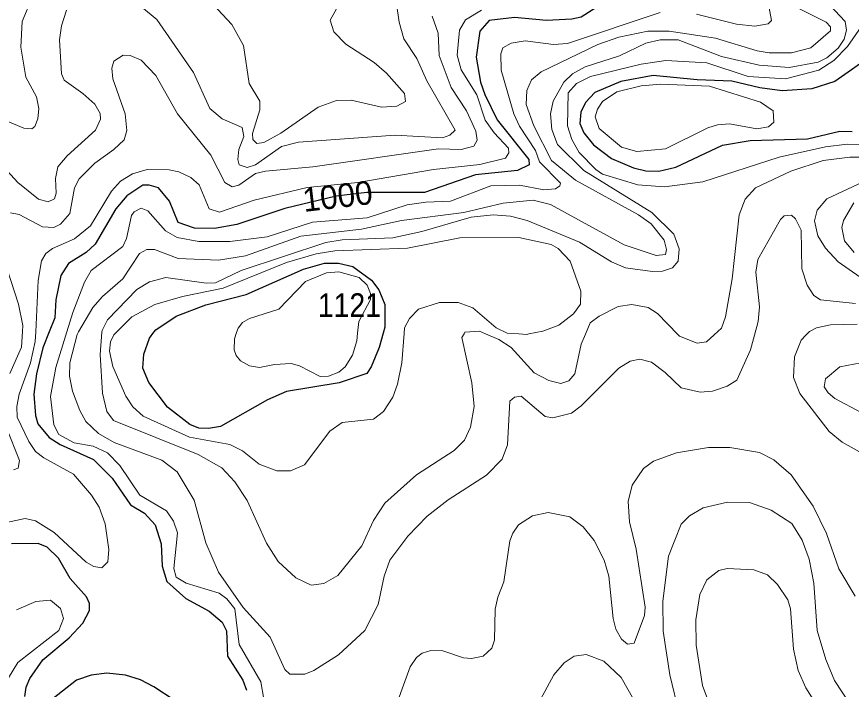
# Model space of a CAD drawing. Extents: x 473.9 to 500, y 7733.1 to 7760.8.
# Drawn here: x 479.07 to 481.9, y 7739.929 to 7742.209 of the extents above; entities that cross this region are included whole.
import ezdxf
from ezdxf.enums import TextEntityAlignment as Align

# ---------------------------------------------------------------- set-up
doc = ezdxf.new("R2010")
doc.units = 0
doc.header["$LTSCALE"] = 0.032
doc.layers.add('1', color=7, linetype='Continuous', lineweight=25)
doc.layers.add('2', color=7, linetype='Continuous', lineweight=13)
doc.layers.add('21', color=7, linetype='Continuous')
doc.layers.add('61', color=7, linetype='Continuous')

msp = doc.modelspace()

# ---------------------------------------------------------------- linework, layer by layer
at = {"layer": '1'}
for points in [[(481.0493, 7742.2496), (480.9842, 7742.2075), (480.9529, 7742.2003), (480.866, 7742.1958), (480.7586, 7742.2062), (480.6717, 7742.196), (480.6409, 7742.1598), (480.6279, 7742.0722), (480.6431, 7741.9876), (480.6572, 7741.9454), (480.699, 7741.8597), (480.8072, 7741.7253), (480.8075, 7741.707), (480.7685, 7741.6876), (480.6264, 7741.6727), (480.4528, 7741.6134), (480.2574, 7741.613), (480.1533, 7741.6001), (479.9797, 7741.5588), (479.8172, 7741.5043), (479.7406, 7741.4906), (479.6731, 7741.4918), (479.6173, 7741.511), (479.5883, 7741.5841), (479.5506, 7741.6288), (479.52, 7741.6381), (479.4977, 7741.6381), (479.4442, 7741.6014), (479.4062, 7741.5576), (479.336, 7741.4374), (479.3058, 7741.4094), (479.2456, 7741.3723), (479.2195, 7741.3317), (479.2031, 7741.2486), (479.1994, 7741.1878), (479.1808, 7741.1409), (479.159, 7741.0859), (479.1372, 7740.9983), (479.1289, 7740.9297), (479.1338, 7740.8567), (479.142, 7740.8288), (479.1807, 7740.7827), (479.2183, 7740.7591), (479.3309, 7740.7081), (479.3943, 7740.6447), (479.4558, 7740.5541), (479.5036, 7740.5257), (479.5396, 7740.4868), (479.56, 7740.4224), (479.5633, 7740.3459), (479.5796, 7740.2945), (479.6438, 7740.2366), (479.7234, 7740.1937), (479.7673, 7740.1566), (479.7811, 7740.1265)], [(481.9763, 7742.0816), (481.8439, 7741.9894), (481.7658, 7741.9639), (481.6658, 7741.9577), (481.5895, 7741.9679), (481.4954, 7741.9899), (481.3774, 7741.9945), (481.2284, 7742.0092), (481.1182, 7741.989), (481.0309, 7741.9516), (480.9991, 7741.9177), (480.9831, 7741.8853), (480.9791, 7741.8472), (480.9935, 7741.815), (481.0258, 7741.7751), (481.087, 7741.7281), (481.1611, 7741.6967), (481.2033, 7741.6867), (481.2473, 7741.6852), (481.3046, 7741.6987), (481.4633, 7741.7733), (481.5568, 7741.789), (481.7511, 7741.7953), (481.861, 7741.8209), (481.9032, 7741.8195)], [(479.0977, 7739.9039), (479.102, 7739.9364), (479.1144, 7739.9652), (479.1592, 7740.0285), (479.2484, 7740.1032), (479.2946, 7740.1527), (479.3171, 7740.1964), (479.3169, 7740.22), (479.3073, 7740.2419), (479.2516, 7740.3044), (479.2121, 7740.3732), (479.1734, 7740.411), (479.1428, 7740.4228), (479.0522, 7740.4219)], [(479.7811, 7740.1265), (479.7852, 7740.0411), (479.8373, 7739.9597), (479.8493, 7739.9256)], [(479.6727, 7739.8471), (479.5355, 7739.937), (479.4897, 7739.9609), (479.4393, 7739.9773), (479.3762, 7739.983), (479.323, 7739.9772), (479.2727, 7739.9599), (479.1628, 7739.8728)]]:
    msp.add_lwpolyline(points, dxfattribs=at)
msp.add_lwpolyline([(480.2995, 7741.0878), (480.2726, 7741.022), (480.2572, 7740.9999), (480.1642, 7740.9677), (479.9855, 7740.9387), (479.9212, 7740.9097), (479.7615, 7740.8202), (479.7204, 7740.813), (479.6879, 7740.8145), (479.6572, 7740.8265), (479.5811, 7740.885), (479.5182, 7740.9684), (479.4982, 7741.0173), (479.501, 7741.0648), (479.5202, 7741.1194), (479.5355, 7741.1393), (479.5417, 7741.1473), (479.6109, 7741.1943), (479.7117, 7741.2318), (479.8483, 7741.2673), (480.0424, 7741.353), (480.1134, 7741.3738), (480.1613, 7741.3731), (480.2099, 7741.3627), (480.273, 7741.3159), (480.2983, 7741.2827), (480.3179, 7741.233), (480.3187, 7741.1562), (480.3129, 7741.1357)], close=True, dxfattribs=at)
at = {"layer": '2'}
for points in [[(479.1239, 7742.2775), (479.0893, 7742.193), (479.0847, 7742.106), (479.1011, 7742.0039), (479.1373, 7741.9378), (479.1459, 7741.8977), (479.1425, 7741.8623), (479.1324, 7741.8372), (479.1215, 7741.8291), (479.0948, 7741.8312), (479.025, 7741.8608)], [(480.1645, 7742.2535), (480.1333, 7742.1967), (480.1461, 7742.1578), (480.1866, 7742.1159), (480.2819, 7742.0533), (480.3238, 7742.0171), (480.3849, 7741.9487), (480.3887, 7741.9214), (480.3586, 7741.9053), (480.3071, 7741.9022), (480.2042, 7741.9255), (480.1549, 7741.9251), (480.0927, 7741.9025), (479.9656, 7741.8142), (479.9083, 7741.7821), (479.8842, 7741.779), (479.8707, 7741.7925), (479.8695, 7741.8129), (479.8952, 7741.8934), (479.8943, 7741.9228), (479.8581, 7741.9823), (479.8396, 7742.111), (479.7999, 7742.1824), (479.7212, 7742.2684)], [(481.612, 7742.2889), (481.6292, 7742.1966), (481.618, 7742.1846), (481.5728, 7742.177), (481.5108, 7742.1837), (481.3749, 7742.2174)], [(481.1835, 7741.0475), (481.1502, 7741.041), (481.1114, 7741.0171), (480.9837, 7740.8895), (480.9509, 7740.8651), (480.8876, 7740.849), (480.8626, 7740.8538), (480.7804, 7740.9226), (480.7578, 7740.9193), (480.742, 7740.9053), (480.7348, 7740.758), (480.7159, 7740.7092), (480.6627, 7740.6545), (480.5335, 7740.571), (480.4621, 7740.5152), (480.3962, 7740.4485), (480.3354, 7740.3663), (480.316, 7740.3121), (480.2961, 7740.2161), (480.2501, 7740.1282), (480.161, 7740.0459), (480.0782, 7739.9923), (480.0477, 7739.9796), (479.9969, 7739.9796), (479.9795, 7739.9955), (479.9302, 7740.1057), (479.8385, 7740.2062), (479.7544, 7740.3261), (479.7117, 7740.4257), (479.6716, 7740.5699), (479.6146, 7740.6664), (479.562, 7740.7056), (479.4008, 7740.7654), (479.348, 7740.7964), (479.3052, 7740.8372), (479.2839, 7740.8744), (479.2601, 7740.9399), (479.2499, 7740.9901), (479.2504, 7741.0357), (479.275, 7741.1317), (479.2801, 7741.1405), (479.3284, 7741.2228), (479.3607, 7741.2599), (479.43, 7741.3206), (479.4872, 7741.4065), (479.5117, 7741.4203), (479.5374, 7741.4196), (479.6178, 7741.3893), (479.754, 7741.3838), (479.8457, 7741.398), (480.0332, 7741.4649), (480.2391, 7741.4888), (480.3753, 7741.5186), (480.5864, 7741.5451), (480.7198, 7741.5763), (480.8212, 7741.5871), (480.8801, 7741.5725), (481.13, 7741.4355), (481.2382, 7741.3999), (481.2695, 7741.4023), (481.2732, 7741.4195), (481.2658, 7741.4516), (481.2214, 7741.507), (481.1789, 7741.5371), (480.9654, 7741.6546), (480.8837, 7741.722), (480.8235, 7741.8393), (480.798, 7741.9112), (480.7996, 7741.9588), (480.8158, 7741.9951), (480.8484, 7742.0223), (481.0401, 7742.1151), (481.1117, 7742.1397), (481.2097, 7742.1594), (481.2821, 7742.1594), (481.4399, 7742.1365), (481.5807, 7742.0937), (481.621, 7742.087), (481.6976, 7742.087), (481.7629, 7742.1033), (481.8296, 7742.1608), (481.8298, 7742.1741), (481.8143, 7742.1909), (481.6838, 7742.2563)], [(481.8272, 7742.2479), (481.8786, 7742.193), (481.8842, 7742.1635), (481.8763, 7742.1329), (481.8555, 7742.102), (481.8173, 7742.0698), (481.788, 7742.0547), (481.6894, 7742.0365), (481.5873, 7742.0444), (481.4594, 7742.0739), (481.3124, 7742.1302), (481.2517, 7742.1305), (481.2034, 7742.1192), (481.1139, 7742.0769), (480.9976, 7742.0396), (480.9547, 7742.015), (480.9256, 7741.9871), (480.889, 7741.9227), (480.8796, 7741.8802), (480.8852, 7741.827), (480.9036, 7741.7755), (480.9927, 7741.6872), (481.2238, 7741.5452), (481.2977, 7741.4722), (481.3168, 7741.4225), (481.3132, 7741.3799), (481.2942, 7741.3572), (481.2593, 7741.3469), (481.2258, 7741.3451), (481.1342, 7741.3579), (481.0866, 7741.3776), (480.9784, 7741.445), (480.8013, 7741.5178), (480.744, 7741.533), (480.6855, 7741.5371), (480.611, 7741.5298), (480.4437, 7741.4808), (480.3459, 7741.4588), (480.1742, 7741.4527), (480.1183, 7741.4436), (479.8318, 7741.3481), (479.7448, 7741.3073), (479.713, 7741.3059), (479.5763, 7741.3248), (479.5203, 7741.3099), (479.4781, 7741.2845), (479.3781, 7741.181), (479.3598, 7741.1456), (479.3593, 7741.1401), (479.3529, 7741.0637), (479.3614, 7740.9327), (479.3757, 7740.8711), (479.3986, 7740.8399), (479.6856, 7740.7249), (479.7657, 7740.6792), (479.8099, 7740.6322), (479.8514, 7740.5689), (479.9175, 7740.4242), (479.957, 7740.3622), (480.0163, 7740.3068), (480.0686, 7740.282), (480.1118, 7740.2873), (480.1596, 7740.3149), (480.2409, 7740.4156), (480.2805, 7740.5012), (480.3185, 7740.5598), (480.426, 7740.6556), (480.5537, 7740.7384), (480.5881, 7740.7737), (480.6087, 7740.8172), (480.6212, 7740.887), (480.613, 7740.9678), (480.5795, 7741.122), (480.5869, 7741.1344), (480.5901, 7741.1398)], [(479.4752, 7742.2572), (479.545, 7742.1992), (479.6698, 7742.0193), (479.7257, 7741.8982), (479.7668, 7741.8633), (479.8351, 7741.8338), (479.8403, 7741.8033), (479.8238, 7741.7588), (479.8197, 7741.7251), (479.8251, 7741.7068), (479.8516, 7741.698), (479.8804, 7741.7071), (479.9676, 7741.769), (480.0262, 7741.7839), (480.3538, 7741.8073), (480.514, 7741.7985), (480.5388, 7741.8071), (480.5566, 7741.8243), (480.4604, 7741.9917), (480.4274, 7742.067), (480.3833, 7742.1343), (480.3671, 7742.1906), (480.358, 7742.2529)], [(479.0202, 7740.491), (479.099, 7740.5078), (479.1338, 7740.5), (479.1977, 7740.4602), (479.3059, 7740.3595), (479.3322, 7740.3455), (479.3588, 7740.3411), (479.3798, 7740.3614), (479.3829, 7740.4027), (479.3708, 7740.4901), (479.35, 7740.5458), (479.3239, 7740.5864), (479.2632, 7740.6583), (479.1626, 7740.7135), (479.1343, 7740.7352), (479.1116, 7740.7687), (479.0725, 7740.8511), (479.0712, 7740.8879), (479.0785, 7740.929), (479.1166, 7741.0353), (479.1332, 7741.108), (479.1348, 7741.1411), (479.1435, 7741.3148), (479.1545, 7741.381), (479.1691, 7741.4061), (479.1913, 7741.423), (479.2659, 7741.4554), (479.3206, 7741.5005), (479.3919, 7741.6173), (479.4224, 7741.6519), (479.4626, 7741.6766), (479.5122, 7741.6908), (479.5872, 7741.6899), (479.6202, 7741.6828), (479.6604, 7741.6642), (479.6887, 7741.6393), (479.7234, 7741.5579), (479.7581, 7741.5469), (479.8752, 7741.5869), (480.0557, 7741.6297), (480.2265, 7741.6467), (480.483, 7741.6915), (480.6411, 7741.7075), (480.7278, 7741.7298), (480.7391, 7741.7475), (480.7372, 7741.7629), (480.6891, 7741.8148), (480.6591, 7741.858), (480.6303, 7741.9443), (480.5776, 7742.029), (480.5634, 7742.0788), (480.5711, 7742.163), (480.5923, 7742.198), (480.6463, 7742.2313)], [(479.0256, 7741.6999), (479.0737, 7741.6465), (479.1444, 7741.5907), (479.1765, 7741.5814), (479.1988, 7741.592), (479.2038, 7741.611), (479.2014, 7741.6607), (479.21, 7741.6999), (479.2415, 7741.7373), (479.3371, 7741.8242), (479.3549, 7741.8612), (479.3531, 7741.881), (479.3352, 7741.9122), (479.295, 7741.9485), (479.2309, 7741.9937), (479.2228, 7742.0154), (479.2159, 7742.1308), (479.2219, 7742.1786), (479.2392, 7742.231)], [(480.4787, 7742.2107), (480.4988, 7742.1528), (480.5023, 7742.0773), (480.543, 7741.9695), (480.595, 7741.8896), (480.6271, 7741.8215), (480.631, 7741.7904), (480.6204, 7741.7698), (480.5767, 7741.7593), (480.5001, 7741.7607), (480.074, 7741.6997), (479.914, 7741.6852), (479.88, 7741.6771), (479.823, 7741.6382), (479.801, 7741.6323), (479.7758, 7741.647), (479.7281, 7741.74), (479.6151, 7741.8794), (479.5426, 7742.0092), (479.4924, 7742.0622), (479.4554, 7742.0776), (479.4309, 7742.0788), (479.4001, 7742.0588), (479.3928, 7742.0343), (479.3964, 7741.998), (479.4386, 7741.8799), (479.4434, 7741.8232), (479.4344, 7741.7915), (479.3998, 7741.7583), (479.3353, 7741.7128), (479.2818, 7741.6599), (479.2663, 7741.6291), (479.25, 7741.5423), (479.2191, 7741.5057), (479.1961, 7741.4946), (479.1574, 7741.4967), (479.0792, 7741.5379), (479.0491, 7741.5443)], [(481.2522, 7742.223), (480.9375, 7742.1176), (480.8898, 7742.1145), (480.7944, 7742.1273), (480.7467, 7742.1192), (480.7188, 7742.1038), (480.7121, 7742.0831), (480.7128, 7742.0279), (480.7559, 7741.88), (480.7751, 7741.838), (480.8291, 7741.7555), (480.8426, 7741.7169), (480.9144, 7741.6444), (480.9119, 7741.6355), (480.8968, 7741.6252), (480.8572, 7741.6223), (480.7746, 7741.6384), (480.6781, 7741.6361), (480.5407, 7741.5835), (480.4572, 7741.5805), (480.3945, 7741.5709), (480.2584, 7741.5276), (480.0729, 7741.513), (479.9199, 7741.4623), (479.7926, 7741.4464), (479.6875, 7741.4464), (479.6147, 7741.461), (479.5745, 7741.4826), (479.5149, 7741.5507), (479.4925, 7741.5596), (479.4681, 7741.5471), (479.4594, 7741.5346), (479.4431, 7741.457), (479.4297, 7741.43), (479.3224, 7741.3482), (479.3006, 7741.3086), (479.261, 7741.2066), (479.2406, 7741.1406), (479.2032, 7741.0196), (479.1853, 7740.9216), (479.1958, 7740.8257), (479.2133, 7740.7922), (479.2657, 7740.7647), (479.3295, 7740.7533), (479.3777, 7740.7303), (479.4197, 7740.6878), (479.4878, 7740.587), (479.5788, 7740.5334), (479.6025, 7740.4992), (479.6154, 7740.459), (479.6034, 7740.3384), (479.6111, 7740.3094), (479.6446, 7740.2882), (479.7572, 7740.2542), (479.7831, 7740.235), (479.8101, 7740.2012), (479.8245, 7740.0812), (479.8981, 7739.9545), (479.9081, 7739.8951)], [(481.933, 7742.1743), (481.8876, 7742.1079), (481.8406, 7742.0601), (481.7896, 7742.0273), (481.6767, 7741.9979), (481.5502, 7742.0066), (481.4107, 7742.0529), (481.2709, 7742.0605), (481.1872, 7742.0477), (481.0153, 7742.0067), (480.9679, 7741.9825), (480.9398, 7741.9512), (480.9373, 7741.8387), (480.9522, 7741.793), (480.9775, 7741.7487), (481.0338, 7741.6906), (481.0564, 7741.675), (481.1766, 7741.6392), (481.2671, 7741.6321), (481.3961, 7741.6488), (481.6552, 7741.7325), (481.8128, 7741.7679), (481.8857, 7741.7767), (481.9395, 7741.7752)], [(480.5901, 7741.1398), (480.6389, 7741.1431), (480.66, 7741.1341), (480.7044, 7741.1152), (480.7472, 7741.0871), (480.8251, 7741.0017), (480.8749, 7740.9756), (480.9149, 7740.9657), (480.9423, 7740.9748), (480.9624, 7740.9984), (480.9845, 7741.0984), (480.9989, 7741.1325), (481.015, 7741.1707), (481.0447, 7741.1941), (481.1099, 7741.226), (481.1564, 7741.2332), (481.2118, 7741.2233), (481.2424, 7741.2023), (481.3123, 7741.1311), (481.3173, 7741.126), (481.3773, 7741.102), (481.4091, 7741.1064), (481.4354, 7741.1305), (481.46, 7741.1531), (481.4738, 7741.1918), (481.4962, 7741.3206), (481.5196, 7741.5376), (481.5403, 7741.5903), (481.5751, 7741.629), (481.6948, 7741.6849), (481.8051, 7741.721), (481.8945, 7741.7326), (481.9665, 7741.7325)], [(481.9403, 7741.6493), (481.8167, 7741.5912), (481.7842, 7741.553), (481.775, 7741.517), (481.7861, 7741.466), (481.8119, 7741.4242), (481.8559, 7741.3784), (481.9299, 7741.326)], [(481.9089, 7741.5776), (481.8739, 7741.5182), (481.8683, 7741.4941), (481.8773, 7741.4497), (481.9093, 7741.4095)], [(481.9141, 7741.2364), (481.7957, 7741.2493), (481.7729, 7741.2643), (481.7498, 7741.299), (481.7324, 7741.3546), (481.7295, 7741.4849), (481.7106, 7741.5235), (481.6968, 7741.5363), (481.6723, 7741.5344), (481.6596, 7741.522), (481.5825, 7741.3858), (481.5764, 7741.3429), (481.5884, 7741.225), (481.5844, 7741.1761), (481.5717, 7741.1299), (481.5581, 7741.0802), (481.5119, 7740.9766), (481.4789, 7740.9562), (481.429, 7740.94), (481.3872, 7740.9365), (481.3231, 7740.9509), (481.2694, 7741.0033), (481.2223, 7741.0383), (481.1835, 7741.0475)], [(479.024, 7741.3947), (479.0767, 7741.234), (479.0911, 7741.1623), (479.0897, 7741.1413), (479.0861, 7741.0888), (479.0466, 7740.9999)], [(482.0376, 7740.6733), (481.8689, 7740.7669), (481.8249, 7740.8031), (481.7254, 7740.9312), (481.7035, 7740.9864), (481.7078, 7741.0556), (481.7295, 7741.1123), (481.7463, 7741.1291), (481.7586, 7741.1413), (481.7822, 7741.1544), (481.8299, 7741.1649), (481.9199, 7741.1668)], [(481.9318, 7741.0355), (481.8609, 7741.0217), (481.8124, 7740.9817), (481.808, 7740.9543), (481.8213, 7740.9336), (481.8444, 7740.9148), (481.9339, 7740.8671)], [(479.0356, 7740.8149), (479.0801, 7740.7049), (479.0749, 7740.6781), (479.0592, 7740.6731)], [(480.6513, 7740.0408), (480.6807, 7740.0683), (480.6902, 7740.0956), (480.6926, 7740.2007), (480.7013, 7740.2409), (480.7224, 7740.2933), (480.7424, 7740.4322), (480.752, 7740.4584), (480.7719, 7740.4859), (480.8191, 7740.5168), (480.8721, 7740.5282), (480.9455, 7740.5137), (480.9914, 7740.4793), (481.0279, 7740.433), (481.0626, 7740.3665), (481.078, 7740.3123), (481.093, 7740.169), (481.1021, 7740.1325), (481.1208, 7740.0983), (481.1414, 7740.082), (481.1635, 7740.0857), (481.1989, 7740.1792), (481.201, 7740.2076), (481.1703, 7740.4038), (481.1474, 7740.4965), (481.1431, 7740.5651), (481.1573, 7740.6209), (481.195, 7740.6773), (481.2289, 7740.7026), (481.3078, 7740.7307), (481.4156, 7740.7484), (481.4879, 7740.7484), (481.5887, 7740.7311), (481.6375, 7740.7066), (481.6961, 7740.6561), (481.7704, 7740.5493), (481.8159, 7740.4575), (481.858, 7740.3368), (481.9125, 7740.2443)], [(481.8946, 7739.8794), (481.8429, 7739.9584), (481.8134, 7740.0302), (481.7845, 7740.1283), (481.7732, 7740.2891), (481.7573, 7740.3705), (481.7331, 7740.4348), (481.6982, 7740.4907), (481.6281, 7740.5364), (481.5545, 7740.5618), (481.4804, 7740.5635), (481.3974, 7740.5442), (481.3513, 7740.5168), (481.3228, 7740.4883), (481.2798, 7740.3797), (481.2611, 7740.2279), (481.2619, 7740.1256), (481.285, 7739.9783), (481.3176, 7739.8426)], [(481.5694, 7740.3336), (481.4794, 7740.3385), (481.4511, 7740.332), (481.4105, 7740.3002), (481.386, 7740.2505), (481.373, 7740.1643), (481.3742, 7740.0784), (481.3949, 7739.9413), (481.4242, 7739.8662)], [(481.7877, 7739.8676), (481.7463, 7739.9342), (481.7199, 7739.9927), (481.7041, 7740.0645), (481.6937, 7740.2017), (481.6849, 7740.2322), (481.6499, 7740.2842), (481.6163, 7740.3164), (481.5694, 7740.3336)], [(479.0425, 7739.9674), (479.0747, 7740.0193), (479.2133, 7740.1286), (479.2294, 7740.169), (479.2192, 7740.2027), (479.1845, 7740.2306), (479.1355, 7740.227), (479.0701, 7740.1978)], [(480.3397, 7739.8276), (480.4045, 7740.0045), (480.4255, 7740.0364), (480.4449, 7740.0515), (480.4744, 7740.0609), (480.5146, 7740.0587), (480.5853, 7740.035), (480.6127, 7740.0329), (480.6513, 7740.0408)], [(481.1622, 7739.8936), (481.1193, 7739.9683), (481.0615, 7740.0237), (481.0013, 7740.0464), (480.9601, 7740.0408), (480.926, 7740.019), (480.891, 7739.9777), (480.8235, 7739.8523)]]:
    msp.add_lwpolyline(points, dxfattribs=at)
for points in [[(481.5801, 7741.8283), (481.6196, 7741.8362), (481.6375, 7741.852), (481.635, 7741.8903), (481.5921, 7741.9192), (481.4193, 7741.9736), (481.2539, 7741.9803), (481.1877, 7741.9745), (481.1046, 7741.9539), (481.0568, 7741.9213), (481.0391, 7741.8952), (481.0321, 7741.8696), (481.0453, 7741.8303), (481.1211, 7741.7669), (481.1724, 7741.7519), (481.2697, 7741.7609), (481.4131, 7741.8326), (481.4466, 7741.8428), (481.4873, 7741.8458)], [(480.1323, 7740.8035), (480.1743, 7740.8335), (480.2798, 7740.8442), (480.3141, 7740.8707), (480.3457, 7740.9193), (480.3613, 7740.9631), (480.3759, 7741.0358), (480.3841, 7741.1354), (480.3856, 7741.1543), (480.4023, 7741.1864), (480.4324, 7741.2178), (480.5034, 7741.2404), (480.567, 7741.2404), (480.6172, 7741.2218), (480.6964, 7741.154), (480.7331, 7741.1359), (480.773, 7741.1336), (480.8, 7741.132), (480.8072, 7741.1334), (480.8536, 7741.1426), (480.9088, 7741.1632), (480.9581, 7741.2012), (480.9814, 7741.2344), (480.9835, 7741.2784), (480.9463, 7741.3799), (480.9058, 7741.423), (480.8822, 7741.4372), (480.7733, 7741.4609), (480.5726, 7741.4599), (480.3955, 7741.4239), (480.1485, 7741.4155), (480.0859, 7741.405), (479.9851, 7741.376), (479.7706, 7741.2886), (479.6328, 7741.2608), (479.5382, 7741.2338), (479.461, 7741.1919), (479.4089, 7741.1399), (479.3997, 7741.1307), (479.3882, 7741.1066), (479.3848, 7741.0746), (479.3967, 7741.0228), (479.4399, 7740.9226), (479.4643, 7740.886), (479.4991, 7740.8545), (479.6566, 7740.7835), (479.7927, 7740.7589), (479.8358, 7740.7377), (479.8924, 7740.6916), (479.9523, 7740.6697), (479.999, 7740.6697), (480.0464, 7740.69)], [(480.2084, 7741.0619), (480.2232, 7741.1102), (480.2262, 7741.1361), (480.2307, 7741.1756), (480.27, 7741.2506), (480.2698, 7741.2711), (480.2584, 7741.299), (480.231, 7741.3245), (480.1624, 7741.3442), (480.1212, 7741.3406), (480.05, 7741.3117), (479.9592, 7741.2175), (479.8591, 7741.1858), (479.8359, 7741.172), (479.8208, 7741.1526), (479.8158, 7741.138), (479.8084, 7741.1166), (479.8079, 7741.0802), (479.8144, 7741.06), (479.8294, 7741.0421), (479.8592, 7741.0249), (479.8939, 7741.0194), (479.9442, 7741.0298), (480.001, 7741.0329), (480.0289, 7741.0253), (480.0996, 7740.9895), (480.1273, 7740.9903), (480.1626, 7741.0045), (480.1836, 7741.0225)]]:
    msp.add_lwpolyline(points, close=True, dxfattribs=at)

# ---------------------------------------------------------------- texts
at = {"layer": '21', "width": 0.9}
msp.add_text('1121', height=0.08, dxfattribs=at).set_placement((480.0913, 7741.1914))
at = {"layer": '61'}
msp.add_text('1000', height=0.08, rotation=6.71, dxfattribs=at).set_placement((480.1627, 7741.5609), align=Align.CENTER)

doc.saveas('drawing.dxf')
